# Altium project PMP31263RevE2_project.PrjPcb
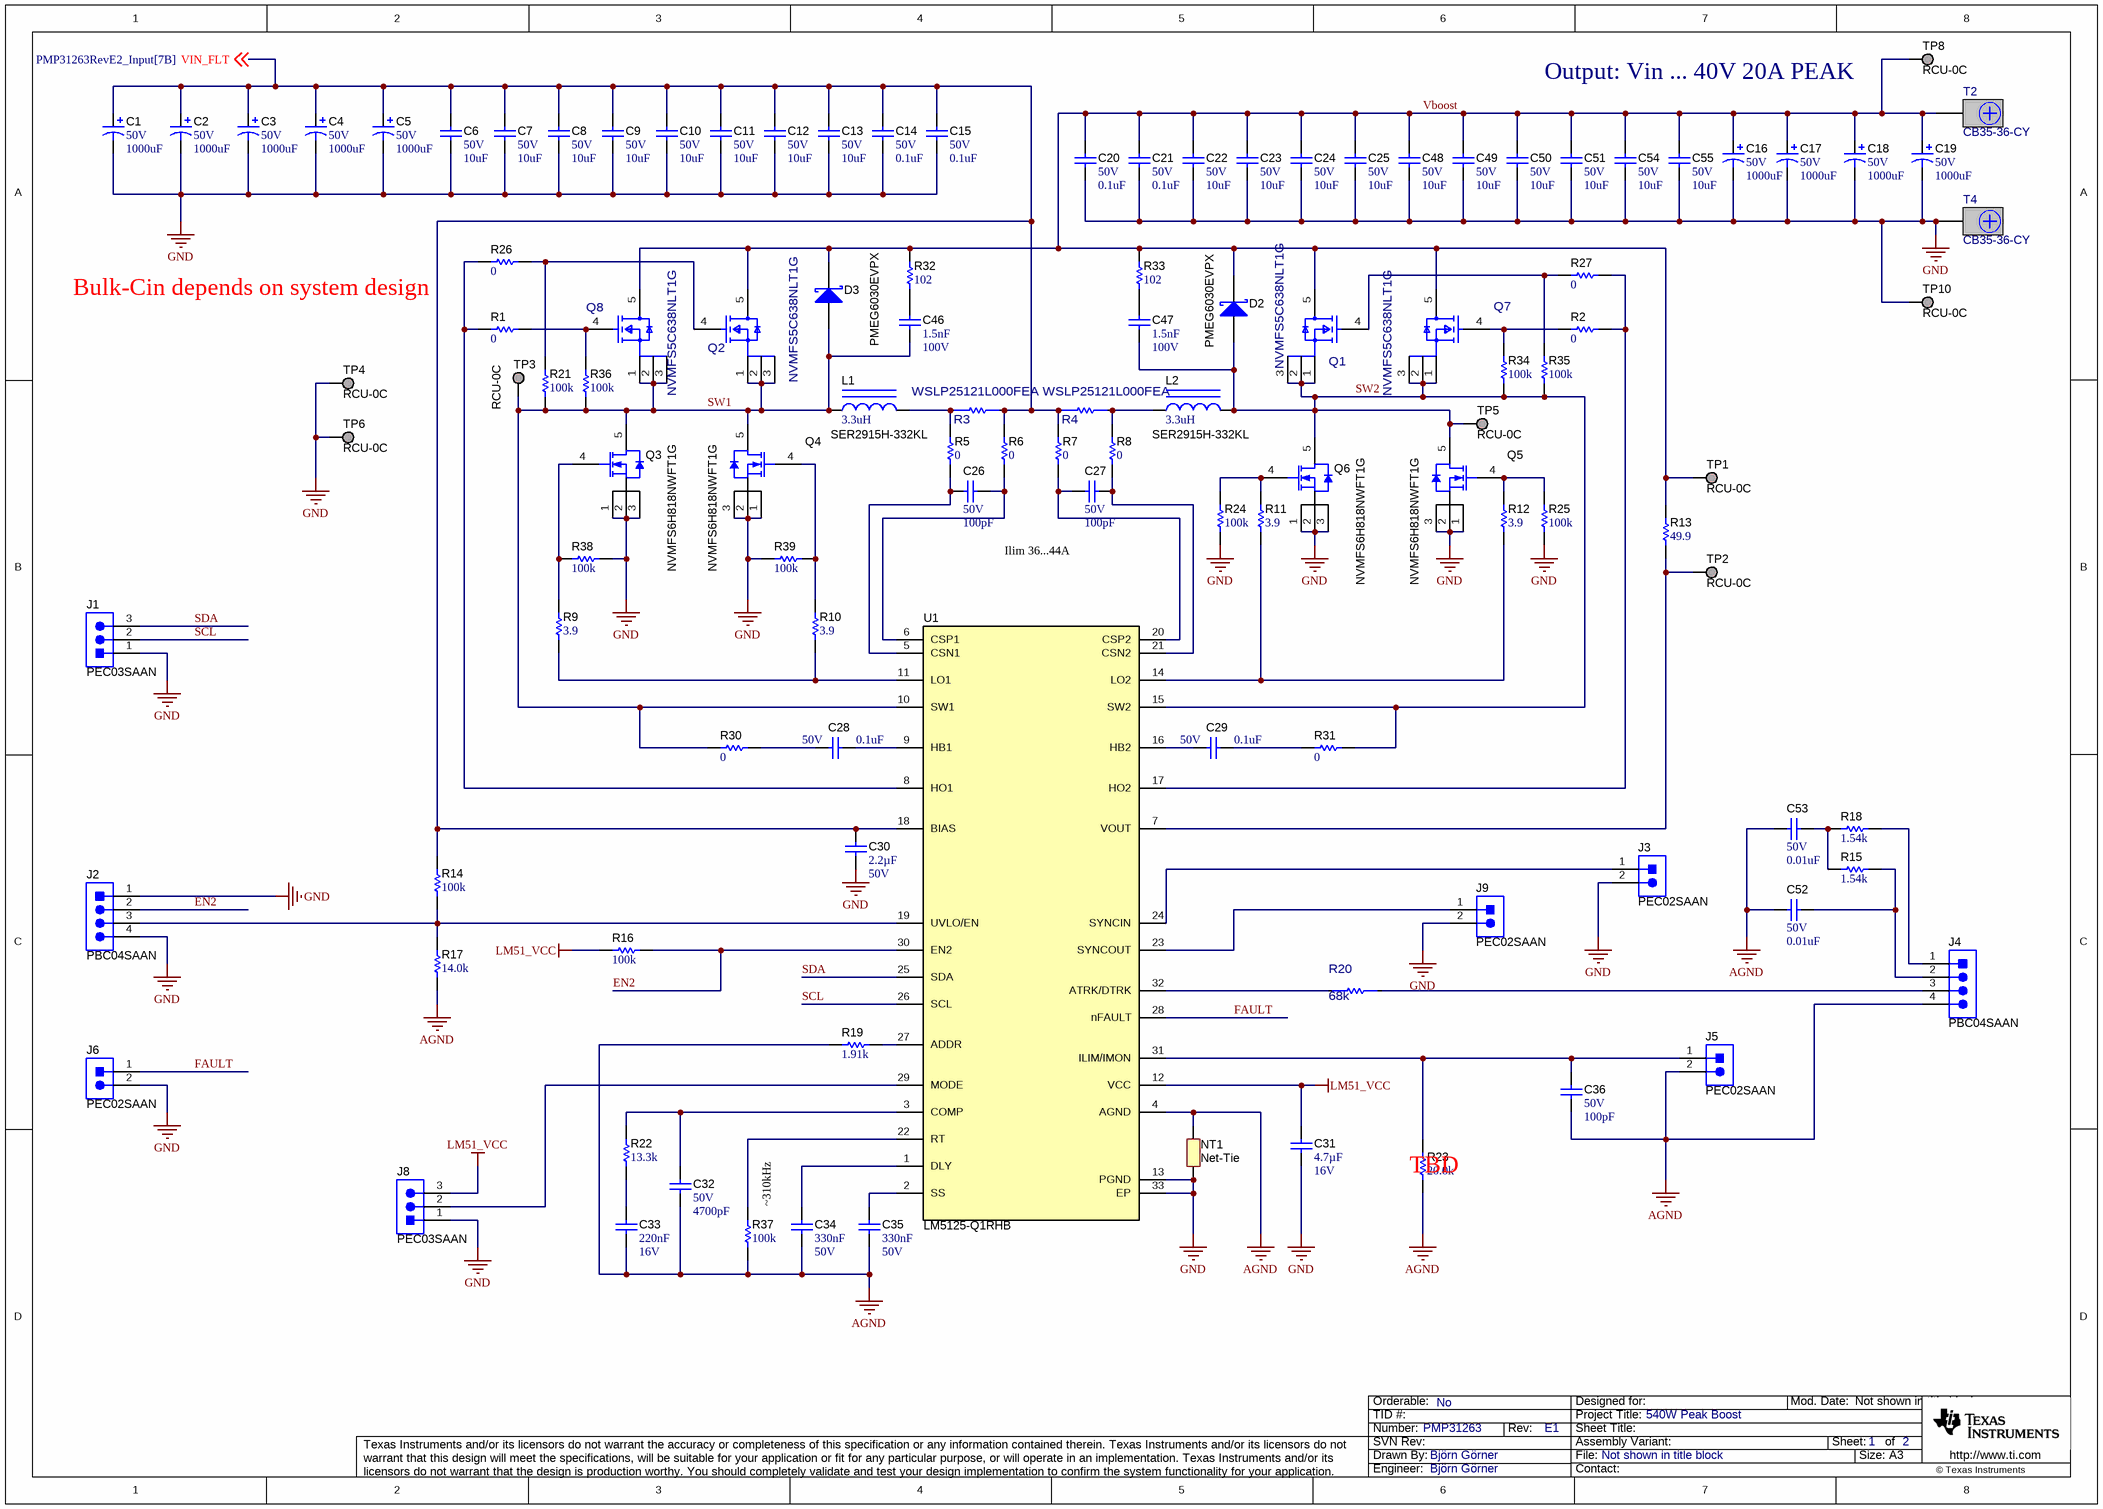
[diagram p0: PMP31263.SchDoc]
SCH_Rev: E1; PRJ_Title: 540W Peak Boost; PRJ_Number: PMP31263; PRJ_Engineer: Björn Görner; EVM_orderable: No; DrawnBy: Björn Görner
2 sheets, 138 parts. Net scope: global (net labels, ports and power ports of the same name join across sheets).
Board file: PMP31263RevE2_board.PcbDoc
Sheets:
  PMP31263.SchDoc
  PMP31263RevE2_Input.SchDoc

## Sheet PMP31263.SchDoc
size A3; Date: Not shown in title block; ApprovedBy: Not shown in title block; CheckedBy: Not shown in title block; Author: Not shown in title block; CompanyName: Not shown in title block; Engineer: Not shown in title block; Organization: Not shown in title block; Address1: Not shown in title block; Address2: Not shown in title block; Address3: Not shown in title block; Address4: Not shown in title block; DocumentNumber: 1; Revision: Use project parameter SCH_Rev; SheetNumber: 1; SheetTotal: 2; PageSetup: Record=PageOptions¦CenterHorizontal=True¦CenterVertical=True¦PrintScale=0.69¦XCorrection=1.00¦YCorrection=1.00¦PrintKind=0¦BorderSize=5000000¦LeftOffset=0¦BottomOffset=0¦Orientation=2¦PaperLength=1000¦PaperWidth=1000¦Scale=100¦PaperSource=15¦PrintQuality=600¦MediaType=1¦DitherType=10¦PaperKind=Letter¦PrintScaleMode=1

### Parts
C1  VDC_V: 50V  ValueDisplayed: 1000uF  [CAPSMT_62_MN0]  (hidden comment: EMVE500GTR102MMN0S)
C2  VDC_V: 50V  ValueDisplayed: 1000uF  [CAPSMT_62_MN0]  (hidden comment: EMVE500GTR102MMN0S)
C3  VDC_V: 50V  ValueDisplayed: 1000uF  [CAPSMT_62_MN0]  (hidden comment: EMVE500GTR102MMN0S)
C4  VDC_V: 50V  ValueDisplayed: 1000uF  [CAPSMT_62_MN0]  (hidden comment: EMVE500GTR102MMN0S)
C5  VDC_V: 50V  ValueDisplayed: 1000uF  [CAPSMT_62_MN0]  (hidden comment: EMVE500GTR102MMN0S)
C6  VDC_V: 50V  ValueDisplayed: 10uF  [1210_270]  (hidden comment: UMJ325KB7106KMHT)
C7  VDC_V: 50V  ValueDisplayed: 10uF  [1210_270]  (hidden comment: UMJ325KB7106KMHT)
C8  VDC_V: 50V  ValueDisplayed: 10uF  [1210_270]  (hidden comment: UMJ325KB7106KMHT)
C9  VDC_V: 50V  ValueDisplayed: 10uF  [1210_270]  (hidden comment: UMJ325KB7106KMHT)
C10  VDC_V: 50V  ValueDisplayed: 10uF  [1210_270]  (hidden comment: UMJ325KB7106KMHT)
C11  VDC_V: 50V  ValueDisplayed: 10uF  [1210_270]  (hidden comment: UMJ325KB7106KMHT)
C12  VDC_V: 50V  ValueDisplayed: 10uF  [1210_270]  (hidden comment: UMJ325KB7106KMHT)
C13  VDC_V: 50V  ValueDisplayed: 10uF  [1210_270]  (hidden comment: UMJ325KB7106KMHT)
C14  VDC_V: 50V  ValueDisplayed: 0.1uF  [0402]  (hidden comment: CGA2B3X7R1H104K050BB)
C15  VDC_V: 50V  ValueDisplayed: 0.1uF  [0402]  (hidden comment: CGA2B3X7R1H104K050BB)
C16  VDC_V: 50V  ValueDisplayed: 1000uF  [CAPSMT_62_MN0]  (hidden comment: EMVE500GTR102MMN0S)
C17  VDC_V: 50V  ValueDisplayed: 1000uF  [CAPSMT_62_MN0]  (hidden comment: EMVE500GTR102MMN0S)
C18  VDC_V: 50V  ValueDisplayed: 1000uF  [CAPSMT_62_MN0]  (hidden comment: EMVE500GTR102MMN0S)
C19  VDC_V: 50V  ValueDisplayed: 1000uF  [CAPSMT_62_MN0]  (hidden comment: EMVE500GTR102MMN0S)
C20  VDC_V: 50V  ValueDisplayed: 0.1uF  [0402]  (hidden comment: CGA2B3X7R1H104K050BB)
C21  VDC_V: 50V  ValueDisplayed: 0.1uF  [0402]  (hidden comment: CGA2B3X7R1H104K050BB)
C22  VDC_V: 50V  ValueDisplayed: 10uF  [1210_270]  (hidden comment: UMJ325KB7106KMHT)
C23  VDC_V: 50V  ValueDisplayed: 10uF  [1210_270]  (hidden comment: UMJ325KB7106KMHT)
C24  VDC_V: 50V  ValueDisplayed: 10uF  [1210_270]  (hidden comment: UMJ325KB7106KMHT)
C25  VDC_V: 50V  ValueDisplayed: 10uF  [1210_270]  (hidden comment: UMJ325KB7106KMHT)
C26  VDC_V: 50V  ValueDisplayed: 100pF  [0402]  (hidden comment: CGA2B2C0G1H101J050BA)
C27  VDC_V: 50V  ValueDisplayed: 100pF  [0402]  (hidden comment: CGA2B2C0G1H101J050BA)
C28  VDC_V: 50V  ValueDisplayed: 0.1uF  [0402]  (hidden comment: CGA2B3X7R1H104K050BB)
C29  VDC_V: 50V  ValueDisplayed: 0.1uF  [0402]  (hidden comment: CGA2B3X7R1H104K050BB)
C30  Cap_F: 2.2µF  VDC_V: 50V  [0805_HV]  (hidden comment: CGA4J3X7R1H225K125AB)
C31  Cap_F: 4.7µF  VDC_V: 16V  [0805_HV]  (hidden comment: CGA4J3X7R1C475K125AE)
C32  VDC_V: 50V  ValueDisplayed: 4700pF  [0402]  (hidden comment: GCM155R71H472KA37D)
C33  Cap_F: 220nF  VDC_V: 16V  [0603]  (hidden comment: CL10B224KO8VPNC)
C34  Cap_F: 330nF  VDC_V: 50V  [0603]  (hidden comment: CGA3E3X7R1H334K080AB)
C35  Cap_F: 330nF  VDC_V: 50V  [0603]  (hidden comment: CGA3E3X7R1H334K080AB)
C36  VDC_V: 50V  ValueDisplayed: 100pF  [0402]  (hidden comment: CGA2B2C0G1H101J050BA)
C46  Cap_F: 1.5nF  VDC_V: 100V  [0603]  (hidden comment: CGA3E2X7R2A152K080AA)
C47  Cap_F: 1.5nF  VDC_V: 100V  [0603]  (hidden comment: CGA3E2X7R2A152K080AA)
C48  VDC_V: 50V  ValueDisplayed: 10uF  [1210_270]  (hidden comment: UMJ325KB7106KMHT)
C49  VDC_V: 50V  ValueDisplayed: 10uF  [1210_270]  (hidden comment: UMJ325KB7106KMHT)
C50  VDC_V: 50V  ValueDisplayed: 10uF  [1210_270]  (hidden comment: UMJ325KB7106KMHT)
C51  VDC_V: 50V  ValueDisplayed: 10uF  [1210_270]  (hidden comment: UMJ325KB7106KMHT)
C52  VDC_V: 50V  ValueDisplayed: 0.01uF  [0402]  (hidden comment: CGA2B3X7R1H103K050BB)
C53  VDC_V: 50V  ValueDisplayed: 0.01uF  [0402]  (hidden comment: CGA2B3X7R1H103K050BB)
C54  VDC_V: 50V  ValueDisplayed: 10uF  [1210_270]  (hidden comment: UMJ325KB7106KMHT)
C55  VDC_V: 50V  ValueDisplayed: 10uF  [1210_270]  (hidden comment: UMJ325KB7106KMHT)
D2  PMEG6030EVPX  [SOD-128]
D3  PMEG6030EVPX  [SOD-128]
J1  PEC03SAAN  [CONN_PEC03SAAN]
J2  PBC04SAAN  [Sullins_xxC04SAAN]
J3  PEC02SAAN  [CONN_PEC02SAAN]
J4  PBC04SAAN  [Sullins_xxC04SAAN]
J5  PEC02SAAN  [CONN_PEC02SAAN]
J6  PEC02SAAN  [CONN_PEC02SAAN]
J8  PEC03SAAN  [CONN_PEC03SAAN]
J9  PEC02SAAN  [CONN_PEC02SAAN]
L1  SER2915H-332KL  ValueDisplayed: 3.3uH  [SER2915H]
L2  SER2915H-332KL  ValueDisplayed: 3.3uH  [SER2915H]
NT1  Net-Tie  [Net-Tie_10milWide_30milLong]  (net tie, no BOM)
Q1  NVMFS5C638NLT1G  [FP-NVMFS5C638NLT1G_DFN5-MFG]
Q2  NVMFS5C638NLT1G  [FP-NVMFS5C638NLT1G_DFN5-MFG]
Q3  NVMFS6H818NWFT1G  [SO-8FL]
Q4  NVMFS6H818NWFT1G  [SO-8FL]
Q5  NVMFS6H818NWFT1G  [SO-8FL]
Q6  NVMFS6H818NWFT1G  [SO-8FL]
Q7  NVMFS5C638NLT1G  [FP-NVMFS5C638NLT1G_DFN5-MFG]
Q8  NVMFS5C638NLT1G  [FP-NVMFS5C638NLT1G_DFN5-MFG]
R1  ValueDisplayed: 0  [0603]  (hidden comment: PMR03EZPJ000)
R2  ValueDisplayed: 0  [0603]  (hidden comment: PMR03EZPJ000)
R3  WSLP25121L000FEA  [FP-WSLP25121L500FEA_2512-MFG]
R4  WSLP25121L000FEA  [FP-WSLP25121L500FEA_2512-MFG]
R5  ValueDisplayed: 0  [0402]  (hidden comment: RK73Z1ETTP)
R6  ValueDisplayed: 0  [0402]  (hidden comment: RK73Z1ETTP)
R7  ValueDisplayed: 0  [0402]  (hidden comment: RK73Z1ETTP)
R8  ValueDisplayed: 0  [0402]  (hidden comment: RK73Z1ETTP)
R9  ValueDisplayed: 3.9  [0603]  (hidden comment: CRCW06033R90JNEA)
R10  ValueDisplayed: 3.9  [0603]  (hidden comment: CRCW06033R90JNEA)
R11  ValueDisplayed: 3.9  [0603]  (hidden comment: CRCW06033R90JNEA)
R12  ValueDisplayed: 3.9  [0603]  (hidden comment: CRCW06033R90JNEA)
R13  ValueDisplayed: 49.9  [0402]  (hidden comment: CRCW040249R9FKED)
R14  ValueDisplayed: 100k  [0402]  (hidden comment: RMCF0402FT100K)
R15  ValueDisplayed: 1.54k  [0402]  (hidden comment: CRCW04021K54FKED)
R16  ValueDisplayed: 100k  [0402]  (hidden comment: RMCF0402FT100K)
R17  ValueDisplayed: 14.0k  [0402]  (hidden comment: CRCW040214K0FKED)
R18  ValueDisplayed: 1.54k  [0402]  (hidden comment: CRCW04021K54FKED)
R19  ValueDisplayed: 1.91k  [0402]  (hidden comment: CRCW04021K91FKED)
R20  68k  [FP-RMCF0402FT68K0_0402-MFG]
R21  ValueDisplayed: 100k  [0402]  (hidden comment: RMCF0402FT100K)
R22  ValueDisplayed: 13.3k  [0402]  (hidden comment: CRCW040213K3FKED)
R23  ValueDisplayed: 20.0k  [0402]  (hidden comment: CRCW040220K0FKED)
R24  ValueDisplayed: 100k  [0402]  (hidden comment: RMCF0402FT100K)
R25  ValueDisplayed: 100k  [0402]  (hidden comment: RMCF0402FT100K)
R26  ValueDisplayed: 0  [0603]  (hidden comment: PMR03EZPJ000)
R27  ValueDisplayed: 0  [0603]  (hidden comment: PMR03EZPJ000)
R30  ValueDisplayed: 0  [0603]  (hidden comment: PMR03EZPJ000)
R31  ValueDisplayed: 0  [0603]  (hidden comment: PMR03EZPJ000)
R32  ValueDisplayed: 102  [1206]  (hidden comment: CRCW1206102RFKEA)
R33  ValueDisplayed: 102  [1206]  (hidden comment: CRCW1206102RFKEA)
R34  ValueDisplayed: 100k  [0402]  (hidden comment: RMCF0402FT100K)
R35  ValueDisplayed: 100k  [0402]  (hidden comment: RMCF0402FT100K)
R36  ValueDisplayed: 100k  [0402]  (hidden comment: RMCF0402FT100K)
R37  ValueDisplayed: 100k  [0402]  (hidden comment: RMCF0402FT100K)
R38  ValueDisplayed: 100k  [0402]  (hidden comment: RMCF0402FT100K)
R39  ValueDisplayed: 100k  [0402]  (hidden comment: RMCF0402FT100K)
T2  CB35-36-CY  [CB35-36-CY]
T4  CB35-36-CY  [CB35-36-CY]
TP1  RCU-0C  [TE_RCU]
TP2  RCU-0C  [TE_RCU]
TP3  RCU-0C  [TE_RCU]
TP4  RCU-0C  [TE_RCU]
TP5  RCU-0C  [TE_RCU]
TP6  RCU-0C  [TE_RCU]
TP8  RCU-0C  [TE_RCU]
TP10  RCU-0C  [TE_RCU]
U1  LM5125-Q1RHB  [PCBComponent_1]

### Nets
AGND: C32.2 C33.2 C34.2 C35.2 C36.2 C52.2 C53.2 J4.4 J5.2 NT1.1 R17.1 R19.1 R23.1 R37.2 U1.4(AGND)
GND: C1.2(-) C2.2(-) C3.2(-) C4.2(-) C5.2(-) C6.2 C7.2 C8.2 C9.2 C10.2 C11.2 C12.2 C13.2 C14.2 C15.2 C16.2(-) C17.2(-) C18.2(-) C19.2(-) C20.2 C21.2 C22.2 C23.2 C24.2 C25.2 C30.2 C31.2 C48.2 C49.2 C50.2 C51.2 C54.2 C55.2 J1.1 J2.1 J2.4 J3.2 J6.2 J8.1 J9.2 NT1.2 Q3.1(S) Q3.2(S) Q3.3(S) Q4.1(S) Q4.2(S) Q4.3(S) Q5.1(S) Q5.2(S) Q5.3(S) Q6.1(S) Q6.2(S) Q6.3(S) R24.1 R25.1 R38.1 R39.2 T4.1 TP4.1 TP6.1 TP10.1 U1.13(PGND) U1.33(EP)
LM51_VCC: C31.1 J8.3 R16.2 U1.12(VCC)
EN2: J2.2 R16.1 U1.30(EN2)
FAULT: J6.1 U1.28(nFAULT)
SCL: J1.2 U1.26(SCL)
SDA: J1.3 U1.25(SDA)
SW1: C46.2 D3.2(A) L1.1 Q2.1(S) Q2.2(S) Q2.3(S) Q3.5(D) Q4.5(D) Q8.1(S) Q8.2(S) Q8.3(S) R21.1 R30.2 R36.1 TP3.1 U1.10(SW1)
SW2: C47.2 D2.2(A) L2.2 Q1.1(S) Q1.2(S) Q1.3(S) Q5.5(D) Q6.5(D) Q7.1(S) Q7.2(S) Q7.3(S) R31.1 R34.1 R35.1 TP5.1 U1.15(SW2)
Vboost: C16.1(+) C17.1(+) C18.1(+) C19.1(+) C20.1 C21.1 C22.1 C23.1 C24.1 C25.1 C48.1 C49.1 C50.1 C51.1 C54.1 C55.1 D2.1(K) D3.1(K) Q1.5(D) Q2.5(D) Q7.5(D) Q8.5(D) R13.2 R32.2 R33.2 T2.1 TP1.1 TP8.1
VIN_FLT: C1.1(+) C2.1(+) C3.1(+) C4.1(+) C5.1(+) C6.1 C7.1 C8.1 C9.1 C10.1 C11.1 C12.1 C13.1 C14.1 C15.1 C30.1 R3.2 R4.1 R6.2 R7.2 R14.2 U1.18(BIAS) ; off-sheet VIN_FLT
NetC26_1: C26.1 R6.1 U1.6(CSP1)
NetC26_2: C26.2 R5.1 U1.5(CSN1)
NetC27_1: C27.1 R8.1 U1.21(CSN2)
NetC27_2: C27.2 R7.1 U1.20(CSP2)
NetC28_1: C28.1 R30.1
NetC28_2: C28.2 U1.9(HB1)
NetC29_1: C29.1 U1.16(HB2)
NetC29_2: C29.2 R31.2
NetC32_1: C32.1 R22.2 U1.3(COMP)
NetC33_1: C33.1 R22.1
NetC34_1: C34.1 U1.1(DLY)
NetC35_1: C35.1 U1.2(SS)
NetC36_1: C36.1 J5.1 R23.2 U1.31(ILIM/IMON)
NetC46_1: C46.1 R32.1
NetC47_1: C47.1 R33.1
NetC52_1: C52.1 J4.2 R15.2
NetC53_1: C53.1 R15.1 R18.1
NetJ2_3: J2.3 R14.1 R17.2 U1.19(UVLO/EN)
NetJ3_1: J3.1 U1.24(SYNCIN)
NetJ4_1: J4.1 R18.2
NetJ4_3: J4.3 R20.2
NetJ8_2: J8.2 U1.29(MODE)
NetJ9_1: J9.1 U1.23(SYNCOUT)
NetL1_2: L1.2 R3.1 R5.2
NetL2_1: L2.1 R4.2 R8.2
NetQ1_4: Q1.4(G) R27.1 R35.2
NetQ2_4: Q2.4(G) R21.2 R26.2
NetQ3_4: Q3.4(G) R9.2 R38.2
NetQ4_4: Q4.4(G) R10.2 R39.1
NetQ5_4: Q5.4(G) R12.2 R25.2
NetQ6_4: Q6.4(G) R11.2 R24.2
NetQ7_4: Q7.4(G) R2.1 R34.2
NetQ8_4: Q8.4(G) R1.2 R36.2
NetR1_1: R1.1 R26.1 U1.8(HO1)
NetR2_2: R2.2 R27.2 U1.17(HO2)
NetR9_1: R9.1 R10.1 U1.11(LO1)
NetR11_1: R11.1 R12.1 U1.14(LO2)
NetR13_1: R13.1 TP2.1 U1.7(VOUT)
NetR19_2: R19.2 U1.27(ADDR)
NetR20_1: R20.1 U1.32(ATRK/DTRK)
NetR37_1: R37.1 U1.22(RT)

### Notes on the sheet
- (near TP8) Output: Vin ... 40V 20A PEAK
- Bulk-Cin depends on system design
- Ilim 36...44A
- (near R23) TBD
- ~310kHz

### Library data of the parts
C1-C5 C16-C19 = CMP-0011290-3: CAP, AL, 1000 uF, 50 V, +/- 20%, SMD; Manufacturer: Chemi-Con; TaMin_C: -40°C; Polarized: Y; SizeAreaWB_mm2: 441; Value1: Unknown; U/M: EA; Value: 1000uF; TaMax_C: 105°C; SizeZ_mm: 21.5; SizeX_mm: 19; Cap_Case: MN0; SizeArea_mm2: 361; CompType: Capacitor; Cap_F: 1mF; IRMS_A: 1.2A; AEC Category: Q200
C6-C13 C22-C25 C48-C51 C54 C55 = CMP-0009257-2: CAP, CERM, 10 uF, 50 V, +/- 10%, X7R, AEC-Q200 Grade 1, 1210; Manufacturer: Taiyo Yuden; TaMin_C: -55°C; Polarized: N; SizeAreaWB_mm2: 14.7; Value1: Unknown; U/M: EA; Value: 10uF; TaMax_C: 125°C; SizeZ_mm: 2.7; SizeX_mm: 3.2; SizeY_mm: 2.5; Cap_Case: 1210; SizeArea_mm2: 8; AEC Qualified: Y; Cap_F: 10µF; AEC Grade: 1; AEC Category: Q200
C14 C15 C20 C21 C28 C29 = CMP-0006325-2: CAP, CERM, 0.1 uF, 50 V, +/- 10%, X7R, AEC-Q200 Grade 1, 0402; Manufacturer: TDK; TaMin_C: -55°C; ESR_ohm: 39.064m; Polarized: N; SizeAreaWB_mm2: 3; Value1: 0.039064 ohm; U/M: EA; Value: 0.1uF; TaMax_C: 125°C; SizeZ_mm: 0.6; SizeX_mm: 1; SizeY_mm: 0.5; AEC Qualified: Y; Cap_F: 100nF; IRMS_A: 814.669mA; AEC Category: Q200
C26 C27 C36 = CMP-0006308-2: CAP, CERM, 100 pF, 50 V, +/- 5%, C0G/NP0, AEC-Q200 Grade 1, 0402; Manufacturer: TDK; TaMin_C: -55°C; Polarized: N; SizeAreaWB_mm2: 3; Value1: Unknown; U/M: EA; Value: 100pF; TaMax_C: 125°C; SizeZ_mm: 0.6; SizeX_mm: 1; SizeY_mm: 0.5; AEC Qualified: Y; AEC Category: Q200
C30 = CMP-0007977-2: CAP, CERM, 2.2 uF, 50 V, +/- 10%, X7R, AEC-Q200 Grade 1, 0805; Manufacturer: TDK; TaMin_C: -55°C; ESR_ohm: 3.288m; Polarized: N; SizeAreaWB_mm2: 6.75; Value1: 0.003288 ohm; U/M: EA; Value: 2.2uF; TaMax_C: 125°C; SizeZ_mm: 1.45; SizeX_mm: 2; SizeY_mm: 1.25; Cap_Case: 0805; SizeArea_mm2: 2.5; AEC Qualified: Y; IRMS_A: 3.6003A; AEC Grade: 1; AEC Category: Q200
C31 = CMP-0080701-1: CAP, CERM, 4.7 µF, 16 V,+/- 10%, X7R, AEC-Q200 Grade 1, 0805; Manufacturer: TDK; SizeAreaWB_mm2: 6.75; SizeArea_mm2: 2.5; AEC Qualified: Y; AEC Category: Q200; Value: 4.7uF; TaMax_C: 125°C; SizeZ_mm: 1.45; AEC Grade: 1; Polarized: N; TaMin_C: -55°C; SizeY_mm: 1.25; U/M: EA; SizeX_mm: 2; Cap_Case: 0805
C32 = CMP-0006361-2: CAP, CERM, 4700 pF, 50 V, +/- 10%, X7R, AEC-Q200 Grade 1, 0402; Manufacturer: MuRata; TaMin_C: -55°C; Polarized: N; SizeAreaWB_mm2: 3; Value1: Unknown; U/M: EA; Value: 4700pF; TaMax_C: 125°C; SizeZ_mm: 0.6; SizeX_mm: 1; SizeY_mm: 0.5; AEC Qualified: Y; Cap_F: 4.7nF; AEC Category: Q200
C33 = CMP-0080102-1: CAP, CERM, 0.22 µF, 16 V,+/- 10%, X7R, AEC-Q200 Grade 1, 0603; Manufacturer: Samsung; SizeAreaWB_mm2: 4.68; SizeArea_mm2: 1.28; AEC Qualified: Y; AEC Category: Q200; Value: 0.22uF; TaMax_C: 125°C; SizeZ_mm: 1; Polarized: N; TaMin_C: -55°C; SizeY_mm: 0.8; U/M: EA; SizeX_mm: 1.6; ValueDisplayed: 0.22µF
C34 C35 = CMP-0007095-4: CAP, CERM, 0.33 uF, 50 V, +/- 10%, X7R, AEC-Q200 Grade 1, 0603; Manufacturer: TDK; TaMin_C: -55°C; ESR_ohm: 15.84m; Polarized: N; SizeAreaWB_mm2: 4.68; Value1: 0.01584 ohm; U/M: EA; Value: 0.33uF; TaMax_C: 125°C; SizeZ_mm: 1; SizeX_mm: 1.6; SizeY_mm: 0.8; SizeArea_mm2: 1.28; AEC Qualified: Y; IRMS_A: 1.3135A; AEC Category: Q200
C46 C47 = CMP-0007083-4: CAP, CERM, 1500 pF, 100 V, +/- 10%, X7R, AEC-Q200 Grade 1, 0603; Manufacturer: TDK; TaMin_C: -55°C; ESR_ohm: 1.3543; Polarized: N; SizeAreaWB_mm2: 4.68; Value1: 1.35428 ohm; U/M: EA; Value: 1500pF; TaMax_C: 125°C; SizeZ_mm: 1; SizeX_mm: 1.6; SizeY_mm: 0.8; SizeArea_mm2: 1.28; AEC Qualified: Y; IRMS_A: 289.63mA; AEC Category: Q200
C52 C53 = CMP-0006324-2: CAP, CERM, 0.01 uF, 50 V, +/- 10%, X7R, AEC-Q200 Grade 1, 0402; Manufacturer: TDK; TaMin_C: -55°C; ESR_ohm: 0.3331; Polarized: N; SizeAreaWB_mm2: 3; Value1: 0.333065 ohm; U/M: EA; Value: 0.01uF; TaMax_C: 125°C; SizeZ_mm: 0.6; SizeX_mm: 1; SizeY_mm: 0.5; AEC Qualified: Y; Cap_F: 10nF; IRMS_A: 323.373mA; AEC Category: Q200
D2 D3 = CMP-0077008-3: Diode, Schottky, 60 V, 3 A, SOD-128; Manufacturer: Nexperia; Value2: 0.475V; Green_REACh: Incomplete; Value1: 3A; SizeAreaWB_mm2: 19.6; TJmax_C: 175°C; Vr_V: 60V; SizeY_mm: 2.5; Vf_V: 475mV; SizeX_mm: 4.6; SizeArea_mm2: 11.5; Green_Lifecycle: Not Set; AEC Category: Q101; SizeZ_mm: 1.1; Value: 60V
J1 J8 = CMP-0002338-1: Header, 100mil, 3x1, Tin, TH; Manufacturer: Sullins Connector Solutions; CNHeader: TRUE; Current_A: 3A; Green_Lifecycle: Not Set; Shrouded: N; Gender: Male; Green_REACh: Incomplete; Voltage_V: 1.8kV; Row_Count: 1; Pitch_mm: 2.54; CT: FALSE; Cert_UL: Y
J2 J4 = CMP-0054583-1: Header, 2.54 mm, 4x1, Gold, TH; Manufacturer: Sullins Connector Solutions; CNHeader: TRUE; Current_A: 3A; Green_Lifecycle: Not Set; Shrouded: N; Gender: Male; Green_REACh: Incomplete; Voltage_V: 1.8kV; Row_Count: 1; Pitch_mm: 2.54; CT: FALSE; Cert_UL: Y
J3 J5 J6 J9 = CMP-0002337-1: Header, 100mil, 2x1, Tin, TH; Manufacturer: Sullins Connector Solutions; CNHeader: TRUE; Current_A: 3A; Green_Lifecycle: Not Set; Shrouded: N; Gender: Male; Green_REACh: Incomplete; Voltage_V: 1.8kV; Row_Count: 1; Pitch_mm: 2.54; CT: FALSE; Cert_UL: Y
L1 L2 = CMP-0060853-1: Inductor, Shielded E Core, Ferrite, 3.3 uH, 30 A, 0.00186 ohm, SMD; Manufacturer: Coilcraft; Isat: 68.4A @ 30% inductance drop; Irms: 30A @ 40C rise; Green_Lifecycle: Not Set; SizeAreaWB_mm2: 651.82; DCR_ohm: 1.86m; Green_REACh: Incomplete; Value: 3.3uH; Imax_A: 30A; SizeZ_mm: 15.36; SizeX_mm: 27.9; SizeY_mm: 19.8; SizeArea_mm2: 552.42; Ind_H: 3.3µH; AEC Category: Q200
NT1 = CMP-0078142-6: Single point connection between nets.
Q1 Q2 Q7 Q8 = CMP-0090226-1: N-Channel 60V 26A (Ta), 133A (Tc) 4W (Ta), 100W (Tc) Surface Mount 5-DFN (5x6) (8-SOFL); Manufacturer: ON Semiconductor; Threshold Vgs Min: 1.2V; Input Capacitace At Vds: 2880pF @ 25V; Vgs_V: 20V; Typ Forward Diode Voltage: 0.84V; AEC Grade: Grade 0; Reverse Recovery Time: 42ns; SizeZ_mm: 1.1mm; ChMode: False; Number Of N Channels: 1; AEC Qualified: Yes; Pulse Drain Current: 811A; Turn Off Delay Time: 66ns; TJmax_C: +175°C; QgTyp_nC: 40.7nC @ 10V; Reverse Recovery Charge: 28nC; Standoff Height: 0mm; Rdson45_ohm: 2.6m; Rthja Max: 40.1°C/W; Threshold Vgs Max: 2V; Transconductance: 130S; Turn On Delay Time: 15ns
Q3-Q6 = CMP-0084694-1: MOSFET, N-CH, 80 V, 123 A, AEC-Q101, SO-8FL; Alternate Manufacturer: None; Manufacturer: ON Semiconductor; IdsMax_A: 123A; SizeX_mm: 6.15; VdsMax_V: 80V; SizeY_mm: 5.15; SizeAreaWB_mm2: 58.2725; SizeArea_mm2: 31.6725; Value: 80V; Vgs_V: 20V; ChMode: Enhancement; Value2: 46 nC; ChType: N; QgTyp_nC: 46; SizeZ_mm: 1.1; Value1: ? ohm; AEC Qualified: Y; AEC Category: Q101
R1 R2 R26 R27 R30 R31 = CMP-0086358-1: RES, 0, 0%, 0.25 W, AEC-Q200 Grade 0, 0603; Manufacturer: Rohm; Power_W: 250mW; SizeZ_mm: 1; SizeArea_mm2: 1.28; Value2: 0.25W; SizeAreaWB_mm2: 4.68; Value_Code: 0000; Value: 0; AEC Qualified: Y; AEC Category: Q200; SizeX_mm: 1.6; SizeY_mm: 0.8
R3 R4 = CMP-0093820-1: 1.0 mOhms ±1% 3W Chip Resistor 2512 (6432 Metric) Anti-Sulfur, Automotive AEC-Q200, Current Sense, Moisture Resistant, Pulse Withstanding Metal Element; Manufacturer: Vishay Dale; PartNumber: WSLP25121L500FEA; Value: 1.5m; AEC Qualified: Yes; SizeZ_mm: 0.889mm; TempCo: 275ppm/°C; AEC Grade: Grade 0
R5-R8 = CMP-0027007-2: RES, 0, 5%, 0.063 W, AEC-Q200 Grade 0, 0402; Manufacturer: KOA Speer; Power_W: 63mW; TempCo: ppm/C; Value_Code: 0000; U/M: EA; Value: 0; EIA_Code: E24; SizeX_mm: 1; SizeY_mm: 0.5; SizeZ_mm: 0.6; Value2: 0.063W; AEC Qualified: Y; AEC Category: Q200
R9-R12 = CMP-0025807-4: RES, 3.9, 5%, 0.1 W, AEC-Q200 Grade 0, 0603; Manufacturer: Vishay-Dale; Power_W: 100mW; TempCo: 200 ppm/C; Value_Code: 3R90; Value: 3.9; EIA_Code: E24; SizeX_mm: 1.6; SizeY_mm: 0.8; SizeZ_mm: 1; Value2: 0.1W; SizeArea_mm2: 1.28; AEC Qualified: Y; VDC_V: 75V; AEC Category: Q200; AEC Grade: 0
R13 = CMP-0026404-2: RES, 49.9, 1%, 0.063 W, AEC-Q200 Grade 0, 0402; Manufacturer: Vishay-Dale; Power_W: 63mW; TempCo: 100 ppm/C; Value_Code: 49R9; Value: 49.9; EIA_Code: E96; SizeX_mm: 1; SizeY_mm: 0.5; SizeZ_mm: 0.6; Value2: 0.063W; AEC Qualified: Y; VDC_V: 50V; AEC Category: Q200; AEC Grade: 0
R14 R16 R21 R24 R25 R34-R39 = CMP-0026753-1: RES, 100 k, 1%, 0.063 W, AEC-Q200 Grade 0, 0402; Manufacturer: Stackpole Electronics Inc; Power_W: 63mW; TempCo: 100 ppm/C; U/M: EA; Value: 100k; EIA_Code: E96; SizeX_mm: 1; SizeY_mm: 0.5; SizeZ_mm: 0.6; Value2: 0.063W; AEC Qualified: Y; VDC_V: 50V; AEC Grade: 0; AEC Category: Q200
R15 R18 = CMP-0026089-3: RES, 1.54 k, 1%, 0.063 W, AEC-Q200 Grade 0, 0402; Manufacturer: Vishay-Dale; Power_W: 63mW; TempCo: 100 ppm/C; Value_Code: 1k54; Value: 1.54k; EIA_Code: E96; SizeX_mm: 1; SizeY_mm: 0.5; SizeZ_mm: 0.6; Value2: 0.063W; AEC Qualified: Y; VDC_V: 50V; AEC Category: Q200; AEC Grade: 0
R17 = CMP-0026015-3: RES, 14.0 k, 1%, 0.063 W, AEC-Q200 Grade 0, 0402; Manufacturer: Vishay-Dale; Power_W: 63mW; TempCo: 100 ppm/C; Value_Code: 14k0; Value: 14.0k; EIA_Code: E96; Res_ohm: 14k; SizeX_mm: 1; SizeY_mm: 0.5; SizeZ_mm: 0.6; Value2: 0.063W; AEC Qualified: Y; VDC_V: 50V; AEC Category: Q200; AEC Grade: 0
R19 = CMP-0026098-2: RES, 1.91 k, 1%, 0.063 W, AEC-Q200 Grade 0, 0402; Manufacturer: Vishay-Dale; Power_W: 63mW; TempCo: 100 ppm/C; Value_Code: 1k91; Value: 1.91k; EIA_Code: E96; SizeX_mm: 1; SizeY_mm: 0.5; SizeZ_mm: 0.6; Value2: 0.063W; AEC Qualified: Y; VDC_V: 50V; AEC Category: Q200; AEC Grade: 0
R20 = CMP-0095242-1: 68kΩ ±1% 0.063W 0402 Thick Film Chip Resistor AEC-Q200 compliant; PartNumber: RMCF0402FT68K0; Manufacturer: Stackpole Electronics; AEC Qualified: Yes; TempCo: 100ppm/°C; Power_W: 63mW; AEC Grade: Grade 0; VDC_V: 50V; SizeZ_mm: 0.35mm
R22 = CMP-0026004-3: RES, 13.3 k, 1%, 0.063 W, AEC-Q200 Grade 0, 0402; Manufacturer: Vishay-Dale; Power_W: 63mW; TempCo: 100 ppm/C; Value_Code: 13k3; Value: 13.3k; EIA_Code: E96; SizeX_mm: 1; SizeY_mm: 0.5; SizeZ_mm: 0.6; Value2: 0.063W; AEC Qualified: Y; VDC_V: 50V; AEC Category: Q200; AEC Grade: 0
R23 = CMP-0026162-2: RES, 20.0 k, 1%, 0.063 W, AEC-Q200 Grade 0, 0402; Manufacturer: Vishay-Dale; Power_W: 63mW; TempCo: 100 ppm/C; Value_Code: 20k0; Value: 20.0k; EIA_Code: E96; Res_ohm: 20k; SizeX_mm: 1; SizeY_mm: 0.5; SizeZ_mm: 0.6; Value2: 0.063W; AEC Qualified: Y; VDC_V: 50V; AEC Category: Q200; AEC Grade: 0
R32 R33 = CMP-0016572-3: RES, 102, 1%, 0.25 W, AEC-Q200 Grade 0, 1206; Manufacturer: Vishay-Dale; Power_W: 250mW; TempCo: 100 ppm/C; Value_Code: 102R; Value: 102; EIA_Code: E96; SizeX_mm: 3.2; SizeY_mm: 1.6; SizeZ_mm: 1.35; Value2: 0.25W; SizeArea_mm2: 5.12; AEC Qualified: Y; VDC_V: 200V; AEC Category: Q200; AEC Grade: 0
T2 T4 = CMP-0055442-1: Terminal 50A Lug; Manufacturer: Panduit; CNHeader: FALSE; Green_Lifecycle: Not Set; Cert_CULUS: Y; Green_REACh: Incomplete; Voltage_V: 600V; CompType: Screw Terminal; ContactFinish: Copper
TP1-TP6 TP8 TP10 = CMP-0067620-1: PC Test Point, SMT; Manufacturer: TE Connectivity
U1 = LM5125: Manufacturer: Used in BOM report; CompType: Used in some BOM reports.  Useful for finding later.

## Sheet PMP31263RevE2_Input.SchDoc
size A3; Date: Not shown in title block; ApprovedBy: Not shown in title block; CheckedBy: Not shown in title block; Author: Not shown in title block; CompanyName: Not shown in title block; Engineer: Not shown in title block; Organization: Not shown in title block; Address1: Not shown in title block; Address2: Not shown in title block; Address3: Not shown in title block; Address4: Not shown in title block; DocumentNumber: 1; Revision: Use project parameter SCH_Rev; SheetNumber: 2; SheetTotal: 2; PageSetup: Record=PageOptions¦CenterHorizontal=True¦CenterVertical=True¦PrintScale=0.69¦XCorrection=1.00¦YCorrection=1.00¦PrintKind=0¦BorderSize=5000000¦LeftOffset=0¦BottomOffset=0¦Orientation=2¦PaperLength=1000¦PaperWidth=1000¦Scale=100¦PaperSource=15¦PrintQuality=600¦MediaType=1¦DitherType=10¦PaperKind=Letter¦PrintScaleMode=1
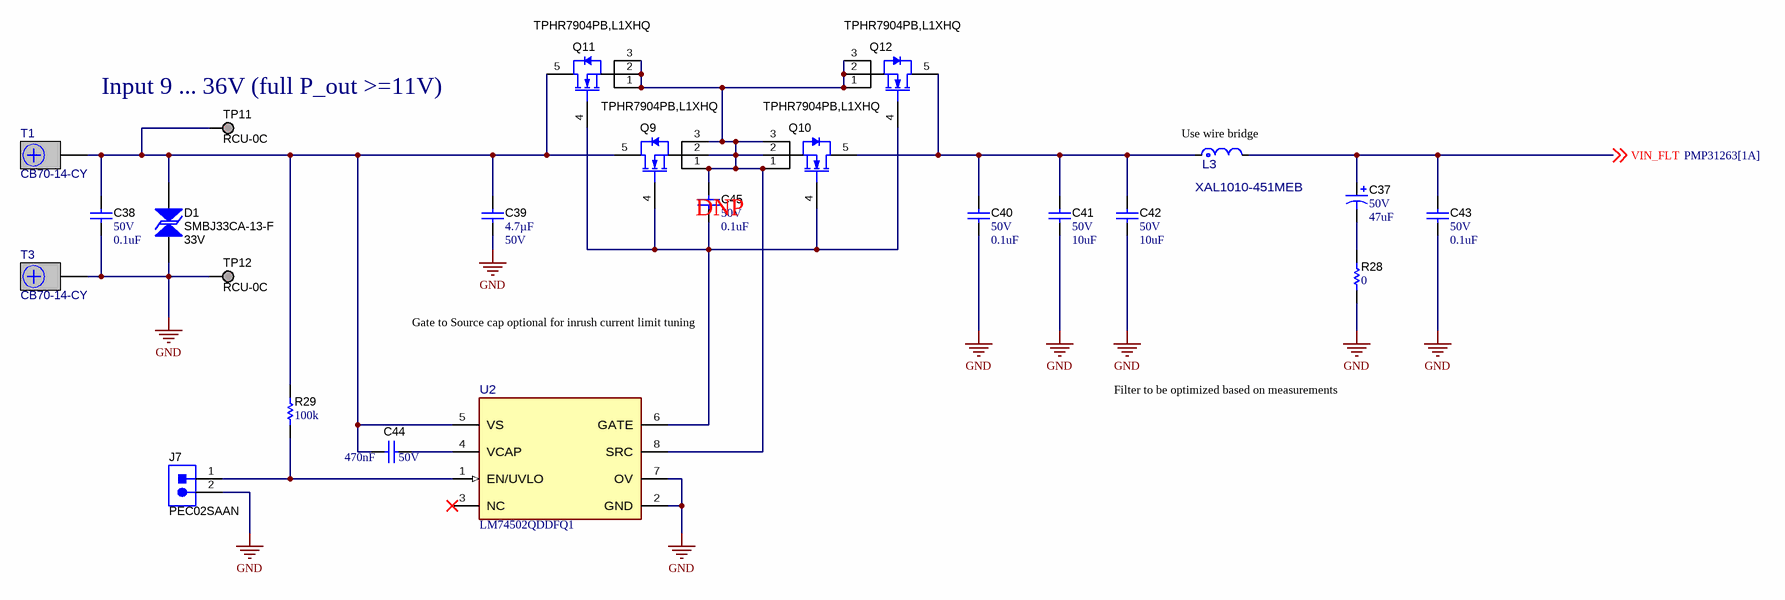
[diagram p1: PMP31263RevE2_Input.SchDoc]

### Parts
C37  VDC_V: 50V  ValueDisplayed: 47uF  [Panasonic_D]  (hidden comment: EEEFT1H470AP)
C38  VDC_V: 50V  ValueDisplayed: 0.1uF  [0402]  (hidden comment: CGA2B3X7R1H104K050BB)
C39  ValueDisplayed: 4.7µF  VDC_V: 50V  [1210_270]  (hidden comment: GCM32ER71H475KA55L)
C40  VDC_V: 50V  ValueDisplayed: 0.1uF  [0402]  (hidden comment: CGA2B3X7R1H104K050BB)
C41  VDC_V: 50V  ValueDisplayed: 10uF  [1210_270]  (hidden comment: UMJ325KB7106KMHT)
C42  VDC_V: 50V  ValueDisplayed: 10uF  [1210_270]  (hidden comment: UMJ325KB7106KMHT)
C43  VDC_V: 50V  ValueDisplayed: 0.1uF  [0402]  (hidden comment: CGA2B3X7R1H104K050BB)
C44  Cap_F: 470nF  VDC_V: 50V  [0603]  (hidden comment: CGA3E3X7R1H474K080AE)
C45  VDC_V: 50V  ValueDisplayed: 0.1uF  [0402]  (hidden comment: CGA2B3X7R1H104K050BB)
D1  SMBJ33CA-13-F  value 33V  [SMB-Bi]
J7  PEC02SAAN  [CONN_PEC02SAAN]
L3  XAL1010-451MEB  [FP-XAL1010-451MEB_SMD2-MFG]
Q9  TPHR7904PB,L1XHQ  [SO-8FL]
Q10  TPHR7904PB,L1XHQ  [SO-8FL]
Q11  TPHR7904PB,L1XHQ  [SO-8FL]
Q12  TPHR7904PB,L1XHQ  [SO-8FL]
R28  ValueDisplayed: 0  [0805_HV]  (hidden comment: ERJ-6GEY0R00V)
R29  ValueDisplayed: 100k  [0402]  (hidden comment: RMCF0402FT100K)
T1  CB70-14-CY  [CB70-14-CY]
T3  CB70-14-CY  [CB70-14-CY]
TP11  RCU-0C  [TE_RCU]
TP12  RCU-0C  [TE_RCU]
U2  LM74502QDDFQ1  [DDF0008A-MFG]

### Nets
GND: C38.2 C39.2 C40.2 C41.2 C42.2 C43.2 D1.1 J7.2 R28.1 T3.1 TP12.1 U2.2(GND) U2.7(OV)
VIN_FLT: C37.1(+) C43.1 L3.2 ; off-sheet VIN_FLT
NetC37_2: C37.2(-) R28.2
NetC38_1: C38.1 C39.1 C44.2 D1.2 Q9.5(D) Q11.5(D) R29.2 T1.1 TP11.1 U2.5(VS)
NetC40_1: C40.1 C41.1 C42.1 L3.1 Q10.5(D) Q12.5(D)
NetC44_1: C44.1 U2.4(VCAP)
NetC45_1: C45.1 Q9.1(S) Q9.2(S) Q9.3(S) Q10.1(S) Q10.2(S) Q10.3(S) Q11.1(S) Q11.2(S) Q11.3(S) Q12.1(S) Q12.2(S) Q12.3(S) U2.8(SRC)
NetC45_2: C45.2 Q9.4(G) Q10.4(G) Q11.4(G) Q12.4(G) U2.6(GATE)
NetJ7_1: J7.1 R29.1 U2.1(EN/UVLO)

Not connected (* = marked no-connect by the designer): U2 3(NC)*

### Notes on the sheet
- (near TP11) Input 9 ... 36V (full P_out >=11V)
- (near L3) Use wire bridge
- (near C45) DNP
- Gate to Source cap optional for inrush current limit tuning
- Filter to be optimized based on measurements

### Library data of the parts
C37 = CMP-0011204-2: CAP, AL, 47 uF, 50 V, +/- 20%, 0.68 ohm, AEC-Q200 Grade 2, SMD; Manufacturer: Panasonic; TaMin_C: -55°C; ESR_ohm: 0.68; Polarized: Y; SizeAreaWB_mm2: 73.96; U/M: EA; Value: 47uF; TaMax_C: 105°C; SizeZ_mm: 6.1; SizeX_mm: 6.6; Cap_Case: 6.3x5.8mm; SizeArea_mm2: 43.56; CompType: Capacitor; Cap_F: 47µF; IRMS_A: 195mA; AEC Grade: 2; AEC Category: Q200
C38 C40 C43 C45 = CMP-0006325-2: as C14 on sheet PMP31263
C39 = CMP-0750153-1: CAP, CERM, 4.7 µF, 50 V,+/- 10%, X7R, AEC-Q200 Grade 1, 1210; Manufacturer: MuRata; Polarized: N; TaMin_C: -55°C; TaMax_C: 125°C; SizeAreaWB_mm2: 14.7; SizeY_mm: 2.5; AEC Category: Q200; Value: 4.7uF; Cap_Case: 1210; AEC Qualified: Y; AEC Grade: 1; SizeArea_mm2: 8; SizeZ_mm: 2.7; U/M: EA; SizeX_mm: 3.2
C41 C42 = CMP-0009257-2: as C6 on sheet PMP31263
C44 = CMP-0007097-4: CAP, CERM, 0.47 uF, 50 V, +/- 10%, X7R, AEC-Q200 Grade 1, 0603; Manufacturer: TDK; TaMin_C: -55°C; Polarized: N; SizeAreaWB_mm2: 4.68; Value1: Unknown; U/M: EA; Value: 0.47uF; TaMax_C: 125°C; SizeZ_mm: 1; SizeX_mm: 1.6; SizeY_mm: 0.8; SizeArea_mm2: 1.28; AEC Qualified: Y; AEC Category: Q200
D1 = CMP-0005564-3: Diode, TVS, Bi, 33 V, SMB; Manufacturer: Diodes Inc.; SizeX_mm: 5.6; Ppk: 600W; SizeAreaWB_mm2: 44.156; SizeZ_mm: 2.6; SizeArea_mm2: 21.336; SizeY_mm: 3.81; AEC Category: Q101
J7 = CMP-0002337-1: as J3 on sheet PMP31263
L3 = CMP-0090776-1: Shielded Power Inductors - XAL1010 0.45uH AEC Q-200 20% 0.72mohm SRF: 66MHz 40A; Manufacturer: Coilcraft; Irms: 53A; Material: Composite; Isat: 70.5A; AEC Grade: Grade 1; TaMin_C: -40°C; TaMax_C: +125°C; DCR_ohm: 720µ; SizeZ_mm: 10mm; AEC Qualified: Yes; Ind_H: 450nH; Test Frequency: 1MHz; Shrouded: true
Q9 Q11 Q12 = CMP-0750168-1: MOSFET, N-CH, 40 V, AEC-Q101, SO-8FL; PartNumber: NVMFS5C670NLWFAFT1G; Alternate Manufacturer: None; Manufacturer: ON Semiconductor; SizeAreaWB_mm2: 58.2725; Value1: 0.0088 ohm; ChType: N; QgTyp_nC: 20; SizeArea_mm2: 31.6725; Vgs_V: 20V; SizeX_mm: 6.15; SizeZ_mm: 1.1; SizeY_mm: 5.15; Value2: 20 nC; IdsMax_A: 17A; AEC Qualified: Y; ChMode: Enhancement; AEC Category: Q101; Rdson45_ohm: 8.8m; VdsMax_V: 60V; Value: 60V
Q10 = CMP-0750168-1: MOSFET, N-CH, 40 V,  AEC-Q101, SO-8FL; PartNumber: NVMFS5C670NLWFAFT1G; Alternate Manufacturer: None; Manufacturer: ON Semiconductor; SizeAreaWB_mm2: 58.2725; Value1: 0.0088 ohm; ChType: N; QgTyp_nC: 20; SizeArea_mm2: 31.6725; Vgs_V: 20V; SizeX_mm: 6.15; SizeZ_mm: 1.1; SizeY_mm: 5.15; Value2: 20 nC; IdsMax_A: 17A; AEC Qualified: Y; ChMode: Enhancement; AEC Category: Q101; Rdson45_ohm: 8.8m; VdsMax_V: 60V; Value: 60V
R28 = CMP-0020616-3: RES, 0, 5%, 0.125 W, AEC-Q200 Grade 0, 0805; Manufacturer: Panasonic; Power_W: 125mW; TempCo: 600 ppm/C; Value_Code: 0000; Value: 0; EIA_Code: E24; SizeX_mm: 2; SizeY_mm: 1.25; SizeZ_mm: 1.45; Value2: 0.125W; SizeArea_mm2: 2.5; AEC Qualified: Y; VDC_V: 150V; AEC Category: Q200; SizeAreaWB_mm2: 6.75
R29 = CMP-0026753-1: as R14 on sheet PMP31263
T1 T3 = CMP-0055443-2: Terminal 90A Lug; Manufacturer: Panduit; Green_Lifecycle: Not Set; Cert_CULUS: Y; Green_REACh: Incomplete; Voltage_V: 600V; CompType: Screw Terminal; ContactFinish: Copper
TP11 TP12 = CMP-0067620-1: as TP1 on sheet PMP31263
U2 = CMP-0092660-1: Reverse Polarity Protection Controller with Over Voltage Protection; Manufacturer: Texas Instruments; AEC Qualified: Yes; AEC Grade: Grade 1; Max Supply Voltage: 60V; Min Supply Voltage: 4V; Nominal Supply Current: 60uA; Number Of Outputs: 1; TaMax_C: +125°C; TaMin_C: -40°C; Standoff Height: 0mm; SizeZ_mm: 1.1mm; TJmax_C: +150°C

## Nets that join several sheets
GND: PMP31263 (63 pins), PMP31263RevE2_Input (13 pins)
VIN_FLT: PMP31263 (22 pins), PMP31263RevE2_Input (C37.1 C43.1 L3.2)

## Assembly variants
Tested: not fitted C3 C4 C5 C16 C17 C19 C45 C46 C47 D2 D3 L3 R32 R33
